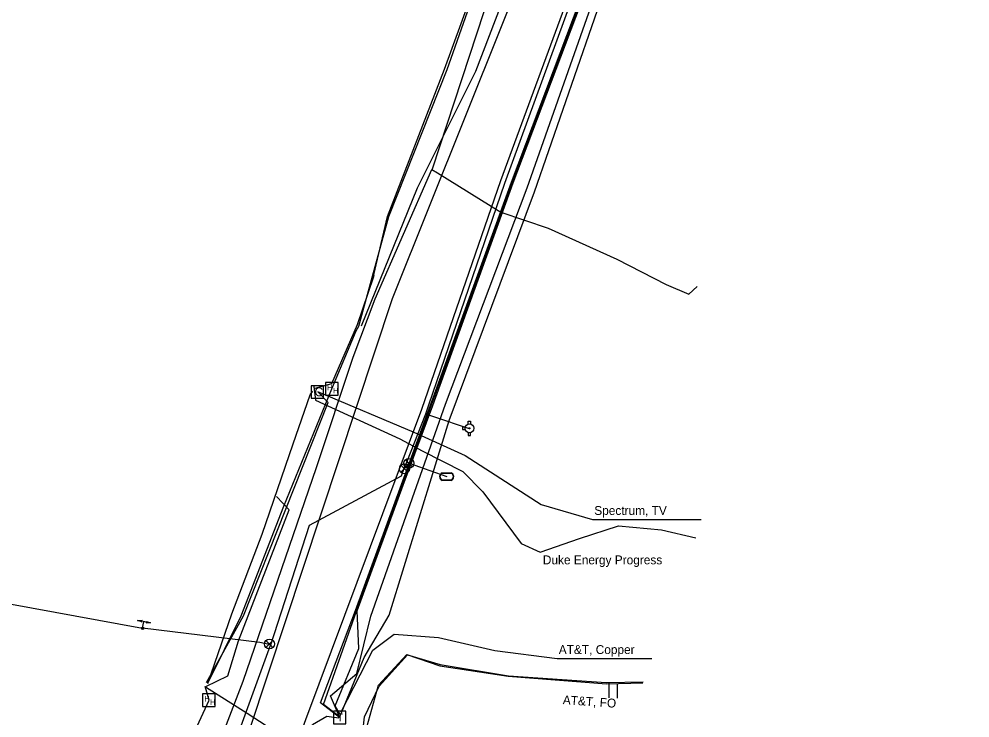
# Model space of a CAD drawing. Extents: x 2070721 to 2083039, y 729290 to 737883.
# Drawn here: x 2081151.9 to 2081580.5, y 733657.9 to 733973 of the extents above; entities that cross this region are included whole.
import ezdxf

# ---------------------------------------------------------------- set-up
doc = ezdxf.new("R2010")
doc.units = 0
for name, color, linetype in [('Cogo Default Point CELL', 7, 'Continuous'), ('COGO Default Point Elevation', 7, 'Continuous'), ('COGO Default Point Number', 7, 'Continuous'), ('Exist Utilities Gas UG Line SUE LOS B Cogo Comment', 7, 'Continuous'), ('Exist Utilities Power UG Cable SUE LOS B Cogo Number', 7, 'Continuous'), ('Exist Utilities Telephone Hand Hole Cogo Elevation', 7, 'Continuous'), ('Exist Utilities Telephone UG Cable Cogo Point CELL', 7, 'Continuous'), ('Exist Utilities Telephone UG Cable SUE LOS C Cogo Comment', 7, 'Continuous'), ('Exist Utilities Telephone UG FO Cogo Point CELL', 7, 'Continuous'), ('Exist Utilities Telephone UG FO SUE LOS B Cogo Comment', 7, 'Continuous'), ('Exist Utilities Telephone UG FO SUE LOS B Cogo Number', 7, 'Continuous'), ('Exist Utilities TV Pedestal CELL', 7, 'Continuous'), ('Exist Utilities TV Pedestal Cogo Elevation', 7, 'Continuous'), ('Exist Utilities TV Pedestal Cogo Number', 7, 'Continuous'), ('Exist Utilities TV UG Cable Cogo Point CELL', 7, 'Continuous'), ('Exist Utilities TV UG Cable SUE LOS C Cogo Comment', 7, 'Continuous'), ('Exist Utilities TV UG Cable SUE LOS C Cogo Elevation', 7, 'Continuous'), ('Exist Utilities TV UG Cable SUE LOS C Cogo Point CELL', 7, 'Continuous'), ('Exist Utilities Water Manhole Cogo Elevation', 7, 'Continuous'), ('Exist Utilities Water Meter CELL', 7, 'Continuous'), ('Exist Utilities Water Meter Cogo Number', 7, 'Continuous'), ('Exist Utilities Water UG Line SUE LOS B Cogo Point CELL', 7, 'Continuous')]:
    doc.layers.add(name, color=color, linetype=linetype)

msp = doc.modelspace()

# ---------------------------------------------------------------- linework, layer by layer
at = {"layer": 'Cogo Default Point CELL'}
msp.add_line((2081286.41, 733804.95), (2081286.41, 733804.95), dxfattribs=at)
msp.add_lwpolyline([(2081283.64, 733802.17), (2081289.19, 733802.17), (2081289.19, 733807.72), (2081283.64, 733807.72), (2081283.64, 733802.17)], dxfattribs=at)
at = {"layer": 'COGO Default Point Elevation'}
for points in [[(2081327.2, 733771.86), (2081324.05, 733768.71), (2081325.62, 733770.28), (2081327.2, 733768.71), (2081324.05, 733771.86)], [(2081329.17, 733774.33), (2081326.02, 733771.18), (2081327.6, 733772.75), (2081329.17, 733771.18), (2081326.02, 733774.33)], [(2081266.35, 733692.87), (2081263.2, 733689.72), (2081264.78, 733691.3), (2081266.35, 733689.72), (2081263.2, 733692.87)]]:
    msp.add_lwpolyline(points, dxfattribs=at)
for centre in [(2081325.62, 733770.28), (2081327.6, 733772.75), (2081264.78, 733691.3)]:
    msp.add_circle(centre, 2.23, dxfattribs=at)
at = {"layer": 'COGO Default Point Number'}
msp.add_line((2081354.91, 733788.53), (2081354.91, 733788.53), dxfattribs=at)
for points in [[(2081353, 733789.04), (2081351.71, 733789.04), (2081351.71, 733788.01), (2081353, 733788.01)], [(2081354.4, 733790.44), (2081354.4, 733791.73), (2081355.43, 733791.73), (2081355.43, 733790.41)], [(2081354.4, 733786.61), (2081354.4, 733785.33), (2081355.43, 733785.33), (2081355.43, 733786.64)]]:
    msp.add_lwpolyline(points, dxfattribs=at)
for radius in [1.98, 0.243]:
    msp.add_circle((2081354.91, 733788.53), radius, dxfattribs=at)
at = {"layer": 'Exist Utilities Power UG Cable SUE LOS B Cogo Number'}
for p, q in [((2081211.24, 733700.84), (2081205.37, 733701.91)), ((2081207.6, 733698.37), (2081208.15, 733701.4)), ((2081208.15, 733701.4), (2081211.24, 733700.84)), ((2081207.6, 733698.37), (2081207.6, 733698.37))]:
    msp.add_line(p, q, dxfattribs=at)
for points in [[(2081205.37, 733701.91), (2081207.37, 733701.9), (2081206.9, 733701.63), (2081207.22, 733701.26)], [(2081211.24, 733700.84), (2081209.24, 733700.86), (2081209.71, 733701.12), (2081209.39, 733701.49)]]:
    msp.add_lwpolyline(points, close=True, dxfattribs=at)
msp.add_circle((2081207.6, 733698.37), 0.517, dxfattribs=at)
at = {"layer": 'Exist Utilities Telephone UG Cable Cogo Point CELL'}
msp.add_line((2081292.89, 733806.33), (2081292.89, 733806.33), dxfattribs=at)
msp.add_lwpolyline([(2081290.02, 733803.45), (2081295.77, 733803.45), (2081295.77, 733809.2), (2081290.02, 733809.2), (2081290.02, 733803.45)], dxfattribs=at)
at = {"layer": 'Exist Utilities Telephone UG Cable SUE LOS C Cogo Comment'}
msp.add_lwpolyline([(2081306.2, 733834.68), (2081331.52, 733896.97), (2081357.74, 733949.48), (2081551.49, 734455.55)], dxfattribs=at)
at = {"layer": 'Exist Utilities Telephone UG FO Cogo Point CELL'}
msp.add_line((2081344.64, 733766.77), (2081344.64, 733766.77), dxfattribs=at)
for points in [[(2081342.61, 733768.47), (2081346.68, 733768.47)], [(2081342.61, 733768.33), (2081346.68, 733768.33)], [(2081346.68, 733765.2), (2081342.58, 733765.2)], [(2081346.68, 733765.07), (2081342.58, 733765.07)]]:
    msp.add_lwpolyline(points, dxfattribs=at)
for centre, radius, start, end in [((2081343.34, 733766.76), 1.86, 113.178, 245.9794), ((2081343.35, 733766.76), 1.73, 115.3009, 243.7824), ((2081345.94, 733766.77), 1.86, 293.6483, 66.3084), ((2081345.95, 733766.77), 1.73, 295.1272, 64.8728)]:
    msp.add_arc(centre, radius, start, end, dxfattribs=at)
at = {"layer": 'Exist Utilities Telephone UG FO SUE LOS B Cogo Comment'}
msp.add_line((2081296.39, 733658.2), (2081296.39, 733658.2), dxfattribs=at)
msp.add_lwpolyline([(2081293.66, 733655.37), (2081299.26, 733655.37), (2081299.26, 733660.97), (2081293.66, 733660.97), (2081293.66, 733655.37)], dxfattribs=at)
at = {"layer": 'Exist Utilities Telephone UG FO SUE LOS B Cogo Number'}
for p, q in [((2081234.64, 733668.79), (2081234.64, 733663.06)), ((2081240.37, 733668.79), (2081234.64, 733668.79)), ((2081240.37, 733663.06), (2081240.37, 733668.79)), ((2081237.51, 733665.93), (2081237.51, 733665.93)), ((2081234.64, 733663.06), (2081240.37, 733663.06))]:
    msp.add_line(p, q, dxfattribs=at)
at = {"layer": 'Exist Utilities TV Pedestal CELL'}
for points in [[(2081305.07, 733834.62), (2081318.51, 733883.96), (2081344.94, 733950.24), (2081370.6, 734023.22), (2081385.26, 734060), (2081415.18, 734152.65), (2081441.55, 734219.41), (2081473.57, 734295.5), (2081490.54, 734320.82), (2081495.24, 734327.83)], [(2081236.98, 733673.69), (2081252.08, 733704.04), (2081271.3, 733753.5), (2081292.85, 733806.31), (2081303.91, 733832.48), (2081305.07, 733834.62)]]:
    msp.add_lwpolyline(points, dxfattribs=at)
at = {"layer": 'Exist Utilities TV Pedestal Cogo Elevation'}
for points in [[(2081335.25, 733795.02), (2081336.53, 733799.05), (2081370.86, 733898.95), (2081404.78, 733992.12), (2081429.05, 734052.38), (2081463.19, 734135.61), (2081490.29, 734199.14)], [(2081326.64, 733773.23), (2081335.25, 733795.02)], [(2081335.25, 733795.02), (2081338.77, 733793.84), (2081354.81, 733788.48)], [(2081265.29, 733690.74), (2081265.37, 733690.97), (2081282.9, 733744.91), (2081324.22, 733767.16), (2081325.31, 733770.15), (2081325.7, 733771.11), (2081326.64, 733773.23)], [(2081326.64, 733773.23), (2081332.01, 733771.35), (2081344.65, 733766.73)], [(2081265.37, 733690.97), (2081260.45, 733691.91), (2081207.6, 733698.37)], [(2081246.63, 733639.55), (2081247.18, 733641.17), (2081265.29, 733690.74)]]:
    msp.add_lwpolyline(points, dxfattribs=at)
at = {"layer": 'Exist Utilities TV Pedestal Cogo Number'}
for points in [[(2081338.03, 733905.19), (2081338.21, 733905.54), (2081364.78, 733986.66), (2081384.36, 734038.69), (2081396.54, 734070.93), (2081397.51, 734073.37)], [(2081312.38, 733846.82), (2081338.03, 733905.19)], [(2081338.03, 733905.19), (2081340.5, 733903.66), (2081369.1, 733885.95), (2081390.43, 733878.76), (2081421.33, 733864.71), (2081443.53, 733853.28), (2081453.74, 733849.03), (2081457.45, 733852.48)], [(2081157.6, 733423.49), (2081157.75, 733423.93), (2081190.43, 733509.93), (2081219.7, 733588.19), (2081252.91, 733674.58), (2081286.02, 733770.88), (2081302.57, 733820.59), (2081312.47, 733846.89)]]:
    msp.add_lwpolyline(points, dxfattribs=at)
at = {"layer": 'Exist Utilities TV UG Cable Cogo Point CELL'}
for points in [[(2080953.21, 732796.69), (2081054.09, 733077.62), (2081111.09, 733245.57), (2081176.08, 733423.78), (2081231.97, 733580.28), (2081320.16, 733847.08), (2081418.84, 734093.09), (2081467.34, 734224.03), (2081494.06, 734287.2), (2081526.74, 734352.01), (2081556, 734404.62), (2081808.13, 734757.73), (2081845.73, 734804.26), (2081874.67, 734821.58), (2081898.66, 734810.94), (2081917.15, 734795.51)], [(2081296.4, 733658.15), (2081287.8, 733664.8), (2081303.6, 733706.37), (2081324.3, 733763.14), (2081337.34, 733798.98), (2081373.91, 733899.45), (2081408.19, 733990.78), (2081432.67, 734050.1), (2081441.11, 734071.31), (2081457.65, 734065.9), (2081441.97, 734074.17), (2081465.76, 734134.1), (2081494.56, 734199.64), (2081510.1, 734235.63), (2081525.23, 734269.67), (2081532.48, 734287.03), (2081544.5, 734311.63), (2081547.42, 734317.11)], [(2081296.31, 733658.4), (2081289.16, 733664.06), (2081304.03, 733706.05), (2081324.8, 733762.93), (2081337.87, 733799.07), (2081374.5, 733899.39), (2081408.89, 733991.2), (2081433.1, 734049.99), (2081442.72, 734074.23), (2081467.51, 734133.17), (2081494.99, 734199.31), (2081510.48, 734235.4), (2081525.69, 734269.34), (2081544.76, 734311.53), (2081547.99, 734317.07)], [(2081296.39, 733658.2), (2081307.45, 733685.25), (2081318.77, 733704.29), (2081345.73, 733792.08), (2081384.21, 733895.19), (2081416.52, 733988.47), (2081438.43, 734048.05), (2081472.15, 734132.3), (2081497.77, 734194.3), (2081521.27, 734233.79), (2081552.24, 734307.58), (2081554.35, 734311.73)], [(2081296.32, 733658.45), (2081292.23, 733667.87), (2081304.13, 733678.02), (2081310.51, 733703.91), (2081344.1, 733799.36), (2081380.98, 733896.99), (2081413.3, 733989.25), (2081435.43, 734048.8), (2081469.68, 734133.31), (2081498.8, 734198.46), (2081514.35, 734234.28), (2081535.34, 734285.71)], [(2081296.61, 733659.46), (2081294.36, 733663.37), (2081305.04, 733689.21), (2081304.27, 733706.32), (2081325.1, 733762.82), (2081338.41, 733798.86), (2081374.68, 733899.14), (2081409.12, 733990.75), (2081435.11, 734049.06), (2081443.22, 734074.28), (2081470.18, 734132.86), (2081499.3, 734198.06), (2081514.4, 734234.31)], [(2081236.99, 733673.45), (2081247.78, 733704.87), (2081261.47, 733740.83), (2081275.48, 733781.49), (2081283.09, 733803.66), (2081284.37, 733805.31)], [(2081297.04, 733660.66), (2081311.38, 733688.44), (2081321.04, 733695.67), (2081341.02, 733694.28), (2081366.4, 733688.3), (2081394.37, 733684.77), (2081437.08, 733684.77)], [(2081236.04, 733672.01), (2081254.79, 733660.17), (2081300.55, 733630.39), (2081327.86, 733624.58)], [(2081252.65, 733568.73), (2081284.23, 733654.98), (2081290.61, 733658.83), (2081296.02, 733657.99)]]:
    msp.add_lwpolyline(points, dxfattribs=at)
at = {"layer": 'Exist Utilities TV UG Cable SUE LOS C Cogo Comment'}
for points in [[(2081284.81, 733807.36), (2081285.5, 733801.28), (2081323.58, 733783.74), (2081333.62, 733778.37)], [(2081333.62, 733778.37), (2081351.93, 733769), (2081360.99, 733759.87), (2081378.22, 733736.62), (2081386.74, 733732.7), (2081404.56, 733738.85), (2081422.08, 733744.58), (2081441.52, 733742.74), (2081456.96, 733739.11)], [(2081236.13, 733672.08), (2081246.06, 733676.96), (2081250.84, 733692.65), (2081273.67, 733751.71), (2081267.99, 733757.78)]]:
    msp.add_lwpolyline(points, dxfattribs=at)
at = {"layer": 'Exist Utilities TV UG Cable SUE LOS C Cogo Elevation'}
for points in [[(2081311.88, 733857.73), (2081318.02, 733883.97), (2081343.7, 733950.47), (2081370.25, 734023.44), (2081378.31, 734051.68)], [(2081311.88, 733857.73), (2081311.69, 733856.75), (2081304.36, 733835.18), (2081292.68, 733808.59), (2081285.24, 733806.52)], [(2081236.49, 733673.89), (2081253.02, 733703.97), (2081291.28, 733800.23), (2081286.6, 733804.95)], [(2081286.47, 733805.11), (2081329.82, 733786.74), (2081352.93, 733776.2), (2081387.16, 733754.14), (2081410.29, 733747.47), (2081440.78, 733747.47), (2081459.29, 733747.47)]]:
    msp.add_lwpolyline(points, dxfattribs=at)
at = {"layer": 'Exist Utilities TV UG Cable SUE LOS C Cogo Point CELL'}
for points in [[(2081248.81, 733567.64), (2081281.2, 733657.22), (2081333.49, 733797.21), (2081369.06, 733900.16), (2081403.11, 733993), (2081427.18, 734053.08), (2081460.75, 734136.42), (2081485.85, 734201.8), (2081501.51, 734239.63), (2081538.45, 734313.8), (2081542.88, 734322.62)], [(2081320.17, 733617.22), (2081309.01, 733633.17), (2081306.6, 733640.45), (2081306.6, 733648.93), (2081307.64, 733658.5), (2081314.26, 733672.29), (2081326.97, 733686.41), (2081341.67, 733682.07), (2081372.57, 733676.97), (2081416.57, 733673.92), (2081433.13, 733674.23)], [(2081306.87, 733635.01), (2081307.14, 733648.47), (2081313.93, 733672.81), (2081326.66, 733686.61), (2081341.59, 733681.48), (2081372.31, 733676.73), (2081416.7, 733673.36), (2081432.98, 733673.8)], [(2081060.57, 733214.24), (2081129.62, 733368.62), (2081142.99, 733409.6), (2081173.13, 733492.79), (2081185.02, 733525.68), (2081211.4, 733608.97), (2081237.57, 733665.91), (2081235.81, 733672.2)]]:
    msp.add_lwpolyline(points, dxfattribs=at)
at = {"layer": 'Exist Utilities Water Manhole Cogo Elevation'}
for p, q in [((2081417.77, 733674.02), (2081417.77, 733667.05)), ((2081421.51, 733673.44), (2081421.51, 733666.83))]:
    msp.add_line(p, q, dxfattribs=at)
at = {"layer": 'Exist Utilities Water UG Line SUE LOS B Cogo Point CELL'}
msp.add_lwpolyline([(2080419.93, 733967.18), (2080512.22, 733915.86), (2080684.81, 733822.52), (2080926.94, 733749.77), (2081207.6, 733698.37)], dxfattribs=at)

# ---------------------------------------------------------------- texts
at = {"layer": 'Cogo Default Point CELL'}
msp.add_text('C', height=4, dxfattribs=at).set_placement((2081285.11, 733802.95))
at = {"layer": 'Exist Utilities Gas UG Line SUE LOS B Cogo Comment'}
msp.add_text('AT&T, FO', height=4, rotation=356.0382, dxfattribs=at).set_placement((2081396.88, 733664.2))
at = {"layer": 'Exist Utilities Telephone Hand Hole Cogo Elevation'}
msp.add_text('Spectrum, TV ', height=4, dxfattribs=at).set_placement((2081411.15, 733749.47))
at = {"layer": 'Exist Utilities Telephone UG Cable Cogo Point CELL'}
for p in [(2081290.8, 733805.68), (2081293.38, 733804.22)]:
    msp.add_text('H', height=2.5, dxfattribs=at).set_placement(p)
at = {"layer": 'Exist Utilities Telephone UG FO SUE LOS B Cogo Comment'}
msp.add_text('T', height=3.42, dxfattribs=at).set_placement((2081295.26, 733656.49))
at = {"layer": 'Exist Utilities Telephone UG FO SUE LOS B Cogo Number'}
for p in [(2081235.42, 733665.33), (2081237.99, 733663.87)]:
    msp.add_text('H', height=2.5, dxfattribs=at).set_placement(p)
at = {"layer": 'Exist Utilities Water Meter CELL'}
msp.add_text('Duke Energy Progress', height=4, dxfattribs=at).set_placement((2081387.98, 733727.21))
at = {"layer": 'Exist Utilities Water Meter Cogo Number'}
msp.add_text('AT&T, Copper', height=4, dxfattribs=at).set_placement((2081395.15, 733686.77))

doc.saveas('drawing.dxf')
